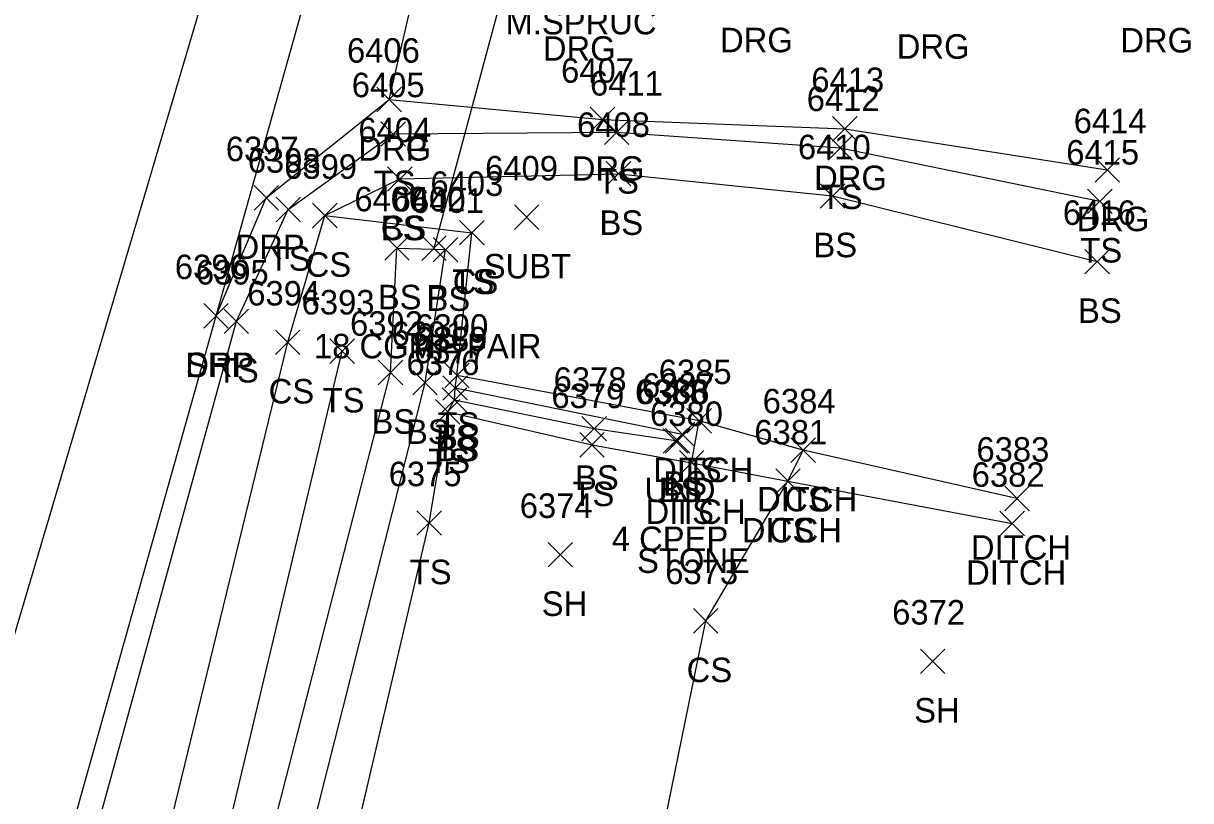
# Model space of a CAD drawing. Extents: x 1443912 to 1445411, y 621446 to 623693.
# Drawn here: x 1444581.9 to 1444677.3, y 621930 to 621993.5 of the extents above; entities that cross this region are included whole.
import ezdxf

# ---------------------------------------------------------------- set-up
doc = ezdxf.new("R2010")
doc.units = 0
for name, color, linetype in [('D_A', 7, 'Continuous'), ('D_C', 7, 'Continuous'), ('D_I', 7, 'Continuous'), ('D_TIC', 7, 'Continuous'), ('DCP', 7, 'Continuous'), ('DD', 7, 'Continuous'), ('L_A', 7, 'Continuous'), ('L_C', 7, 'Continuous'), ('L_I', 7, 'Continuous'), ('L_TIC', 7, 'Continuous'), ('LELB', 7, 'Continuous'), ('P_A', 7, 'Continuous'), ('P_I', 7, 'Continuous'), ('P_TIC', 7, 'Continuous'), ('PET', 7, 'Continuous'), ('PSP', 7, 'Continuous'), ('R_A', 7, 'Continuous'), ('R_I', 7, 'Continuous'), ('R_TIC', 7, 'Continuous'), ('RDG', 7, 'Continuous'), ('RDP', 7, 'Continuous'), ('U_A', 7, 'Continuous'), ('U_I', 7, 'Continuous'), ('U_TIC', 7, 'Continuous')]:
    doc.layers.add(name, color=color, linetype=linetype)

msp = doc.modelspace()

# ---------------------------------------------------------------- linework, layer by layer
at = {"layer": 'D_TIC'}
for points in [[(1444614.473, 621974.129), (1444616.473, 621976.129)], [(1444616.473, 621974.129), (1444614.473, 621976.129)], [(1444636.132, 621960.025), (1444638.132, 621962.025)], [(1444638.132, 621960.025), (1444636.132, 621962.025)], [(1444634.196, 621958.399), (1444636.196, 621960.399)], [(1444636.196, 621958.399), (1444634.196, 621960.399)], [(1444644.622, 621957.639), (1444646.622, 621959.639)], [(1444646.622, 621957.639), (1444644.622, 621959.639)], [(1444635.509, 621956.613), (1444637.509, 621958.613)], [(1444637.509, 621956.613), (1444635.509, 621958.613)], [(1444643.373, 621955.102), (1444645.373, 621957.102)], [(1444645.373, 621955.102), (1444643.373, 621957.102)], [(1444662.077, 621953.694), (1444664.077, 621955.694)], [(1444664.077, 621953.694), (1444662.077, 621955.694)], [(1444661.69, 621951.641), (1444663.69, 621953.641)], [(1444663.69, 621951.641), (1444661.69, 621953.641)]]:
    msp.add_lwpolyline(points, dxfattribs=at)
at = {"layer": 'DCP'}
msp.add_lwpolyline([(1444615.473, 621975.129), (1444625.362, 622011.828)], dxfattribs=at)
at = {"layer": 'DD'}
for points in [[(1444663.077, 621954.694), (1444645.622, 621958.639), (1444637.132, 621961.025)], [(1444636.509, 621957.613), (1444644.373, 621956.102), (1444662.69, 621952.641)]]:
    msp.add_lwpolyline(points, dxfattribs=at)
at = {"layer": 'L_TIC'}
for points in [[(1444611.142, 621983.448), (1444613.142, 621985.448)], [(1444613.142, 621983.448), (1444611.142, 621985.448)], [(1444629.382, 621983.581), (1444631.382, 621985.581)], [(1444631.382, 621983.581), (1444629.382, 621985.581)], [(1444647.65, 621982.317), (1444649.65, 621984.317)], [(1444649.65, 621982.317), (1444647.65, 621984.317)], [(1444611.685, 621979.775), (1444613.685, 621981.775)], [(1444613.685, 621979.775), (1444611.685, 621981.775)], [(1444611.685, 621979.775), (1444613.685, 621981.775)], [(1444613.685, 621979.775), (1444611.685, 621981.775)], [(1444629.542, 621980.206), (1444631.542, 621982.206)], [(1444631.542, 621980.206), (1444629.542, 621982.206)], [(1444647.015, 621978.384), (1444649.015, 621980.384)], [(1444649.015, 621978.384), (1444647.015, 621980.384)], [(1444668.84, 621977.951), (1444670.84, 621979.951)], [(1444670.84, 621977.951), (1444668.84, 621979.951)], [(1444602.574, 621977.286), (1444604.574, 621979.286)], [(1444604.574, 621977.286), (1444602.574, 621979.286)], [(1444605.553, 621976.786), (1444607.553, 621978.786)], [(1444607.553, 621976.786), (1444605.553, 621978.786)], [(1444605.553, 621976.786), (1444607.553, 621978.786)], [(1444607.553, 621976.786), (1444605.553, 621978.786)], [(1444617.566, 621975.389), (1444619.566, 621977.389)], [(1444619.566, 621975.389), (1444617.566, 621977.389)], [(1444617.566, 621975.389), (1444619.566, 621977.389)], [(1444619.566, 621975.389), (1444617.566, 621977.389)], [(1444611.445, 621974.134), (1444613.445, 621976.134)], [(1444613.445, 621974.134), (1444611.445, 621976.134)], [(1444615.415, 621974.005), (1444617.415, 621976.005)], [(1444617.415, 621974.005), (1444615.415, 621976.005)], [(1444615.415, 621974.005), (1444617.415, 621976.005)], [(1444617.415, 621974.005), (1444615.415, 621976.005)], [(1444668.623, 621973.024), (1444670.623, 621975.024)], [(1444670.623, 621973.024), (1444668.623, 621975.024)], [(1444598.334, 621968.157), (1444600.334, 621970.157)], [(1444600.334, 621968.157), (1444598.334, 621970.157)], [(1444602.529, 621966.443), (1444604.529, 621968.443)], [(1444604.529, 621966.443), (1444602.529, 621968.443)], [(1444606.973, 621965.711), (1444608.973, 621967.711)], [(1444608.973, 621965.711), (1444606.973, 621967.711)], [(1444610.926, 621963.975), (1444612.926, 621965.975)], [(1444612.926, 621963.975), (1444610.926, 621965.975)], [(1444613.741, 621963.144), (1444615.741, 621965.144)], [(1444615.741, 621963.144), (1444613.741, 621965.144)], [(1444616.349, 621963.728), (1444618.349, 621965.728)], [(1444618.349, 621963.728), (1444616.349, 621965.728)], [(1444616.349, 621963.728), (1444618.349, 621965.728)], [(1444618.349, 621963.728), (1444616.349, 621965.728)], [(1444616.198, 621962.706), (1444618.198, 621964.706)], [(1444618.198, 621962.706), (1444616.198, 621964.706)], [(1444616.198, 621962.706), (1444618.198, 621964.706)], [(1444618.198, 621962.706), (1444616.198, 621964.706)], [(1444616.149, 621961.733), (1444618.149, 621963.733)], [(1444618.149, 621961.733), (1444616.149, 621963.733)], [(1444616.149, 621961.733), (1444618.149, 621963.733)], [(1444618.149, 621961.733), (1444616.149, 621963.733)], [(1444615.592, 621960.762), (1444617.592, 621962.762)], [(1444617.592, 621960.762), (1444615.592, 621962.762)], [(1444615.592, 621960.762), (1444617.592, 621962.762)], [(1444617.592, 621960.762), (1444615.592, 621962.762)], [(1444627.55, 621959.395), (1444629.55, 621961.395)], [(1444629.55, 621959.395), (1444627.55, 621961.395)], [(1444636.132, 621960.025), (1444638.132, 621962.025)], [(1444638.132, 621960.025), (1444636.132, 621962.025)], [(1444634.377, 621958.402), (1444636.377, 621960.402)], [(1444636.377, 621958.402), (1444634.377, 621960.402)], [(1444634.761, 621958.919), (1444636.761, 621960.919)], [(1444636.761, 621958.919), (1444634.761, 621960.919)], [(1444627.374, 621958.063), (1444629.374, 621960.063)], [(1444629.374, 621958.063), (1444627.374, 621960.063)], [(1444644.622, 621957.639), (1444646.622, 621959.639)], [(1444646.622, 621957.639), (1444644.622, 621959.639)], [(1444635.509, 621956.613), (1444637.509, 621958.613)], [(1444637.509, 621956.613), (1444635.509, 621958.613)], [(1444643.373, 621955.102), (1444645.373, 621957.102)], [(1444645.373, 621955.102), (1444643.373, 621957.102)], [(1444614.083, 621951.692), (1444616.083, 621953.692)], [(1444616.083, 621951.692), (1444614.083, 621953.692)], [(1444624.782, 621949.102), (1444626.782, 621951.102)], [(1444626.782, 621949.102), (1444624.782, 621951.102)], [(1444636.663, 621943.696), (1444638.663, 621945.696)], [(1444638.663, 621943.696), (1444636.663, 621945.696)], [(1444655.195, 621940.398), (1444657.195, 621942.398)], [(1444657.195, 621940.398), (1444655.195, 621942.398)]]:
    msp.add_lwpolyline(points, dxfattribs=at)
at = {"layer": 'LELB'}
for points in [[(1444566.056, 621662.534), (1444540.745, 621668.466), (1444530.657, 621674.021), (1444525.233, 621679.718), (1444521.898, 621690.629), (1444527.674, 621715.457), (1444537.6, 621748.269), (1444544.571, 621771.137), (1444552.879, 621800.551), (1444569.344, 621862.358), (1444584.525, 621915.307), (1444599.334, 621969.157), (1444603.574, 621978.286), (1444612.142, 621984.448), (1444630.382, 621984.581), (1444648.65, 621983.317), (1444669.84, 621978.951)], [(1444562.107, 621788.809), (1444558.44, 621808.652), (1444572.995, 621861.11), (1444590.387, 621913.521), (1444603.529, 621967.443), (1444606.553, 621977.786), (1444612.685, 621980.775)], [(1444612.685, 621980.775), (1444630.542, 621981.206), (1444648.015, 621979.384), (1444669.623, 621974.024)], [(1444606.553, 621977.786), (1444618.566, 621976.389)], [(1444573.525, 621729.963), (1444606.816, 621757.805), (1444615.676, 621770.449), (1444599.049, 621772.866), (1444599.337, 621775.96), (1444583.656, 621779.458), (1444578.875, 621781.944), (1444577.181, 621792.606), (1444574.388, 621805.129), (1444589.716, 621856.093), (1444605.092, 621910.111), (1444615.083, 621952.692), (1444616.592, 621961.762), (1444617.149, 621962.733), (1444617.198, 621963.706), (1444617.349, 621964.728), (1444618.566, 621976.389)], [(1444596.932, 621775.313), (1444596.966, 621774.736), (1444581.989, 621775.148), (1444574.89, 621780.655), (1444572.861, 621790.773), (1444569.594, 621804.752), (1444563.932, 621805.883), (1444584.886, 621857.924), (1444598.239, 621911.806), (1444611.926, 621964.975), (1444612.445, 621975.134), (1444616.415, 621975.005)], [(1444596.932, 621775.313), (1444582.889, 621775.955), (1444576.668, 621781.139), (1444575.689, 621791.72), (1444571.399, 621805.904), (1444586.861, 621857.67), (1444601.369, 621911.126), (1444614.741, 621964.144), (1444616.415, 621975.005)], [(1444599.049, 621772.866), (1444581.278, 621773.15), (1444573.417, 621779.758), (1444571.45, 621790.666), (1444568.624, 621802.829), (1444561.949, 621805.212), (1444579.87, 621859.396), (1444594.916, 621911.852), (1444607.973, 621966.711)], [(1444616.592, 621961.762), (1444628.374, 621959.063), (1444636.509, 621957.613), (1444637.132, 621961.025), (1444617.349, 621964.728)], [(1444617.149, 621962.733), (1444628.55, 621960.395), (1444635.377, 621959.402), (1444635.761, 621959.919), (1444617.198, 621963.706)], [(1444615.676, 621770.449), (1444617.262, 621774.09), (1444611.186, 621801.022), (1444617.47, 621847.687), (1444629.839, 621906.275), (1444637.663, 621944.696), (1444644.373, 621956.102), (1444645.622, 621958.639)]]:
    msp.add_lwpolyline(points, dxfattribs=at)
at = {"layer": 'P_TIC'}
for points in [[(1444596.671, 621968.6), (1444598.671, 621970.6)], [(1444598.671, 621968.6), (1444596.671, 621970.6)]]:
    msp.add_lwpolyline(points, dxfattribs=at)
at = {"layer": 'PET'}
msp.add_lwpolyline([(1444444.373, 621464.942), (1444461.943, 621522.868), (1444475.594, 621570.547), (1444487.991, 621616.259), (1444502.918, 621667.728), (1444516.829, 621718.161), (1444526.411, 621751.485), (1444537.285, 621789.321), (1444558.591, 621864.997), (1444573.586, 621917.928), (1444597.584, 621998.805), (1444610.143, 622044.189), (1444623.481, 622089.496), (1444632.196, 622118.094)], dxfattribs=at)
at = {"layer": 'PSP'}
msp.add_lwpolyline([(1444455.656, 621462.751), (1444472.054, 621519.484), (1444485.131, 621568.302), (1444497.881, 621612.67), (1444505.397, 621638.584), (1444519.015, 621689.585), (1444525.591, 621713.972), (1444535.943, 621748.745), (1444541.511, 621770.147), (1444550.943, 621803.783), (1444567.684, 621862.81), (1444582.555, 621915.85), (1444597.671, 621969.6), (1444608.455, 622008.003), (1444628.131, 622076.356), (1444639.295, 622115.364)], dxfattribs=at)
at = {"layer": 'R_TIC'}
for points in [[(1444610.811, 621986.266), (1444612.811, 621988.266)], [(1444612.811, 621986.266), (1444610.811, 621988.266)], [(1444610.811, 621986.266), (1444612.811, 621988.266)], [(1444612.811, 621986.266), (1444610.811, 621988.266)], [(1444628.237, 621984.632), (1444630.237, 621986.632)], [(1444630.237, 621984.632), (1444628.237, 621986.632)], [(1444648.025, 621983.865), (1444650.025, 621985.865)], [(1444650.025, 621983.865), (1444648.025, 621985.865)], [(1444669.452, 621980.511), (1444671.452, 621982.511)], [(1444671.452, 621980.511), (1444669.452, 621982.511)], [(1444600.777, 621978.228), (1444602.777, 621980.228)], [(1444602.777, 621978.228), (1444600.777, 621980.228)], [(1444596.671, 621968.6), (1444598.671, 621970.6)], [(1444598.671, 621968.6), (1444596.671, 621970.6)]]:
    msp.add_lwpolyline(points, dxfattribs=at)
at = {"layer": 'RDG'}
msp.add_lwpolyline([(1444611.811, 621987.266), (1444629.237, 621985.632), (1444649.025, 621984.865), (1444670.452, 621981.511)], dxfattribs=at)
at = {"layer": 'RDP'}
msp.add_lwpolyline([(1444597.671, 621969.6), (1444601.777, 621979.228), (1444611.811, 621987.266), (1444614.649, 621999.429), (1444608.455, 622008.003)], dxfattribs=at)
at = {"layer": 'U_TIC'}
for points in [[(1444622.04, 621976.655), (1444624.04, 621978.655)], [(1444624.04, 621976.655), (1444622.04, 621978.655)]]:
    msp.add_lwpolyline(points, dxfattribs=at)

# ---------------------------------------------------------------- texts
at = {"layer": 'D_A'}
for s, p in [('P', (1444614.851, 621970.129)), ('DITCH', (1444633.368, 621956.025)), ('UND', (1444632.668, 621954.399)), ('DITCH', (1444641.858, 621953.639)), ('DITCH', (1444632.745, 621952.613)), ('DITCH', (1444640.609, 621951.102)), ('DITCH', (1444659.313, 621949.694)), ('DITCH', (1444658.926, 621947.641))]:
    msp.add_text(s, height=2, dxfattribs=at).set_placement(p)
at = {"layer": 'D_C'}
for s, p in [('18 CGMP FAIR', (1444605.671, 621966.129)), ('4 CPEP', (1444629.991, 621950.399))]:
    msp.add_text(s, height=2, dxfattribs=at).set_placement(p)
at = {"layer": 'D_I'}
for s, p in [('6402', (1444612.088, 621978.129)), ('6385', (1444633.825, 621964.025)), ('6388', (1444631.889, 621962.399)), ('6384', (1444642.315, 621961.639)), ('6380', (1444633.115, 621960.613)), ('6381', (1444641.633, 621959.102)), ('6383', (1444659.77, 621957.694)), ('6382', (1444659.383, 621955.641))]:
    msp.add_text(s, height=2, dxfattribs=at).set_placement(p)
at = {"layer": 'L_A'}
for s, p in [('TS', (1444610.551, 621979.448)), ('TS', (1444628.792, 621979.581)), ('TS', (1444647.059, 621978.317)), ('CS', (1444611.126, 621975.775)), ('BS', (1444611.126, 621975.775)), ('BS', (1444628.983, 621976.206)), ('BS', (1444646.456, 621974.384)), ('TS', (1444668.249, 621973.951)), ('TS', (1444601.984, 621973.286)), ('CS', (1444604.994, 621972.786)), ('CS', (1444604.994, 621972.786)), ('TS', (1444616.976, 621971.389)), ('CS', (1444617.007, 621971.389)), ('BS', (1444610.886, 621970.134)), ('BS', (1444614.856, 621970.005)), ('BS', (1444614.856, 621970.005)), ('BS', (1444668.064, 621969.024)), ('TS', (1444597.744, 621964.157)), ('CS', (1444601.97, 621962.443)), ('TS', (1444606.382, 621961.711)), ('BS', (1444610.367, 621959.975)), ('TS', (1444615.759, 621959.728)), ('TS', (1444615.759, 621959.728)), ('BS', (1444613.182, 621959.144)), ('TS', (1444615.608, 621958.706)), ('BS', (1444615.639, 621958.706)), ('TS', (1444615.559, 621957.733)), ('BS', (1444615.59, 621957.733)), ('TS', (1444615.002, 621956.762)), ('TS', (1444615.002, 621956.762)), ('TS', (1444635.541, 621956.025)), ('BS', (1444626.991, 621955.395)), ('BS', (1444634.202, 621954.919)), ('TS', (1444626.783, 621954.063)), ('BS', (1444633.818, 621954.402)), ('CS', (1444644.063, 621953.639)), ('TS', (1444634.918, 621952.613)), ('CS', (1444642.814, 621951.102)), ('TS', (1444613.493, 621947.692)), ('SH', (1444624.27, 621945.102)), ('CS', (1444636.104, 621939.696)), ('SH', (1444654.684, 621936.398))]:
    msp.add_text(s, height=2, dxfattribs=at).set_placement(p)
at = {"layer": 'L_C'}
for s, p in [('M.SPRUC', (1444621.313, 621992.578)), ('STONE', (1444632.052, 621948.613))]:
    msp.add_text(s, height=2, dxfattribs=at).set_placement(p)
at = {"layer": 'L_I'}
for s, p in [('6405', (1444608.756, 621987.448)), ('6411', (1444628.209, 621987.581)), ('6412', (1444645.91, 621986.317)), ('6408', (1444627.156, 621984.206)), ('6404', (1444609.299, 621983.775)), ('6404', (1444609.299, 621983.775)), ('6410', (1444645.188, 621982.384)), ('6398', (1444600.267, 621981.286)), ('6415', (1444667.1, 621981.951)), ('6399', (1444603.238, 621980.786)), ('6399', (1444603.238, 621980.786)), ('6403', (1444615.181, 621979.389)), ('6403', (1444615.181, 621979.389)), ('6400', (1444608.973, 621978.134)), ('6401', (1444613.596, 621978.005)), ('6401', (1444613.596, 621978.005)), ('6416', (1444666.828, 621977.024)), ('6395', (1444596.027, 621972.157)), ('6394', (1444600.222, 621970.443)), ('6393', (1444604.666, 621969.711)), ('6392', (1444608.619, 621967.975)), ('6391', (1444612.001, 621967.144)), ('6390', (1444613.956, 621967.728)), ('6390', (1444613.956, 621967.728)), ('6389', (1444613.883, 621966.706)), ('6389', (1444613.883, 621966.706)), ('6377', (1444613.842, 621965.733)), ('6377', (1444613.842, 621965.733)), ('6376', (1444613.23, 621964.762)), ('6376', (1444613.23, 621964.762)), ('6378', (1444625.243, 621963.395)), ('6385', (1444633.825, 621964.025)), ('6386', (1444632.015, 621962.402)), ('6387', (1444632.454, 621962.919)), ('6379', (1444625.059, 621962.063)), ('6384', (1444642.315, 621961.639)), ('6380', (1444633.115, 621960.613)), ('6381', (1444641.633, 621959.102)), ('6375', (1444611.776, 621955.692)), ('6374', (1444622.475, 621953.102)), ('6373', (1444634.356, 621947.696)), ('6372', (1444652.888, 621944.398))]:
    msp.add_text(s, height=2, dxfattribs=at).set_placement(p)
at = {"layer": 'P_A'}
msp.add_text('SHP', height=2, dxfattribs=at).set_placement((1444595.207, 621964.6))
at = {"layer": 'P_I'}
msp.add_text('6396', height=2, dxfattribs=at).set_placement((1444594.309, 621972.6))
at = {"layer": 'R_A'}
for s, p in [('DRG', (1444638.83, 621991.119)), ('DRG', (1444638.83, 621991.119)), ('DRG', (1444671.517, 621991.098)), ('DRG', (1444671.517, 621991.098)), ('DRG', (1444624.361, 621990.424)), ('DRG', (1444653.262, 621990.588)), ('DRG', (1444609.299, 621982.266)), ('DRP', (1444609.299, 621982.266)), ('DRG', (1444626.725, 621980.632)), ('DRG', (1444646.513, 621979.865)), ('DRG', (1444667.94, 621976.511)), ('DRP', (1444599.265, 621974.228)), ('DRP', (1444595.16, 621964.6))]:
    msp.add_text(s, height=2, dxfattribs=at).set_placement(p)
at = {"layer": 'R_I'}
for s, p in [('6406', (1444608.37, 621990.266)), ('6406', (1444608.37, 621990.266)), ('6407', (1444625.851, 621988.632)), ('6413', (1444646.285, 621987.865)), ('6414', (1444667.712, 621984.511)), ('6397', (1444598.47, 621982.228)), ('6396', (1444594.309, 621972.6))]:
    msp.add_text(s, height=2, dxfattribs=at).set_placement(p)
at = {"layer": 'U_A'}
msp.add_text('SUBT', height=2, dxfattribs=at).set_placement((1444619.536, 621972.655))
at = {"layer": 'U_I'}
msp.add_text('6409', height=2, dxfattribs=at).set_placement((1444619.646, 621980.655))

doc.saveas('drawing.dxf')
